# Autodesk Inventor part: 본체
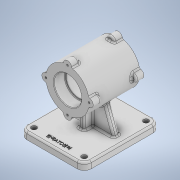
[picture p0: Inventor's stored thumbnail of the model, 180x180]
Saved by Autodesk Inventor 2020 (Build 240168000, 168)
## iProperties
Created: 2022-11
Part Number: 본체
Material: 일반
Document SubType Name: Modeling
Designer: owner
Density: 1 g/cm^3
Appearance: 기본값
Mass: 450.145 g
Surface Area: 796.917 cm^2
Volume: 450.145 cm^3
Author: owner
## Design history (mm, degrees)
sketch "스케치1"
  geometry: C1 r 37 at (0, 0); 1 further point
  constraints: 1 centre point, 1 coincident
  dimensions: "d0" = 74 diameter of C1
extrude "돌출1" new body sketch "스케치1" stored distance "d6" = 87; taper "d7" = 0 deg
sketch "스케치2"
  geometry: A1 r 37 centre (0, 0) between (36.338, 6.969) and (6.969, 36.338) reference; 2 further points
  constraints: 1 coincident
hole "구멍1" sketch "스케치2" at (0, 0) diameter "d8" = 42; stored, may be unused: countersink angle "d12" = 90 deg, drill point angle "d14" = 0 deg; dims "d9" = 8, "d10" = 47, "d11" = 19, "d13" = 10
sketch "스케치3"
  geometry: A1 r 37 centre (0, 0) between (36.338, 6.969) and (6.969, 36.338) reference; 2 further points
  constraints: 1 coincident
hole "구멍2" sketch "스케치3" at (0, 0) diameter "d15" = 42; stored, may be unused: countersink angle "d19" = 90 deg, drill point angle "d21" = 0 deg; dims "d16" = 8, "d17" = 47, "d18" = 19, "d20" = 10
node "작업 평면1"
sketch "스케치4"
  geometry: L1 (-55, 70)-(55, 70); L2 (55, 70)-(55, -60); L3 (55, -60)-(-55, -60); L4 (-55, -60)-(-55, 70); 2 further points
  constraints: 8 end point, 2 parallel, 1 horizontal, 1 midpoint, 1 perpendicular, 1 vertical alignment
  dimensions: "d23" = 110 distance of L2.end L3.end; "d24" = 130 distance of L1.end L2.end; "d25" = 70 distance from line of point (0, 0) L1
extrude "돌출2" join sketch "스케치4" distance "d26" = 12; taper "d27" = 0 deg
node "작업 평면2"
sketch "스케치5"
  geometry: L1 (14, 12)-(29.664, 55.036); L2 (110, 12)-(0, 12) reference; L3 (96, 12)-(80.336, 55.036); A1 r 37 centre (55, 82) between (29.664, 55.036) and (18.662, 75.031) reference; A2 r 37 centre (55, 82) between (80.336, 55.036) and (61.969, 45.662) reference; 4 further points
  constraints: 4 end point, 2 point on circle, 2 point on line, 1 equal length
  dimensions: "d29" = 14 distance of L1.start L2.end; "d30" = 14 distance of L3.start L2.start; "d31" = 110 deg angle of L2 L3
extrude "돌출3" join sketch "스케치5" stored distance "d32" = 10; taper "d33" = 0 deg
sketch "스케치6"
  geometry: C1 r 7 at (0, 37); C2 r 7 at (-37, 0); C3 r 7 at (0, -37); C4 r 7 at (37, 0); 10 further points
  constraints: 4 centre point, 1 vertical alignment, 11 other
  dimensions: "d34" = 14 diameter of C1; "d37" = 360 deg dimension on point (0, 0) C1.centre (derived)
extrude "돌출4" join sketch "스케치6" distance "d39" = 14; taper "d40" = 0 deg
sketch "스케치7"
  geometry: L1 (-70, -60)-(-70, 70) reference; L2 (-70, 20)-(-37, 20); L3 (-70, -20)-(-37, -20); L4 (-37, -43.5)-(-37, 29.5) reference; 1 further point
  constraints: 4 end point, 4 point on line, 2 horizontal
  dimensions: "d41" = 20 distance from line of L3 point (0, 0); "d42" = 40 distance between parallel lines of L2 L3
feature "리브1" sketch "스케치7" dims "d43" = 1, "d44" = 10, "d45" = 0, "d46" = 0, "d47" = 1, "d48" = 1
fillet "모깎기1" dims "d49" = 12
fillet "모깎기2" dims "d50" = 3
fillet "모깎기3" dims "d51" = 3
sketch "스케치8"
  geometry: A1 r 12 centre (-43, 48) between (-43, 60) and (-55, 48) reference; 2 further points
  constraints: 1 coincident
hole "구멍3" sketch "스케치8" at (-43, 48) diameter "d52" = 9; stored, may be unused: countersink angle "d56" = 90 deg, drill point angle "d58" = 0 deg; dims "d53" = 8, "d54" = 47, "d55" = 19, "d57" = 10
sketch "스케치9"
  geometry: A1 r 12 centre (-43, -58) between (-55, -58) and (-43, -70) reference; 2 further points
  constraints: 1 coincident
hole "구멍4" sketch "스케치9" at (-43, -58) diameter "d59" = 9; stored, may be unused: countersink angle "d63" = 90 deg, drill point angle "d65" = 0 deg; dims "d60" = 8, "d61" = 47, "d62" = 19, "d64" = 10
sketch "스케치10"
  geometry: A1 r 12 centre (43, -58) between (43, -70) and (55, -58) reference; 2 further points
  constraints: 1 coincident
hole "구멍5" sketch "스케치10" at (43, -58) diameter "d66" = 9; stored, may be unused: countersink angle "d70" = 90 deg, drill point angle "d72" = 0 deg; dims "d67" = 8, "d68" = 47, "d69" = 19, "d71" = 10
sketch "스케치11"
  geometry: A1 r 12 centre (43, 48) between (55, 48) and (43, 60) reference; 2 further points
  constraints: 1 coincident
hole "구멍6" sketch "스케치11" at (43, 48) diameter "d73" = 9; stored, may be unused: countersink angle "d77" = 90 deg, drill point angle "d79" = 0 deg; dims "d74" = 8, "d75" = 47, "d76" = 19, "d78" = 10
node "스케치12"
sketch "스케치13"
  geometry: A1 r 7 centre (0, 37) between (6.889, 38.239) and (-6.889, 38.239) reference; 2 further points
  constraints: 1 coincident
hole "구멍7" sketch "스케치13" at (0, 37) diameter "d80" = 3.242; stored, may be unused: countersink angle "d84" = 90 deg, drill point angle "d86" = 118 deg; dims "d81" = 8, "d82" = 47, "d83" = 19, "d85" = 10
fillet "모깎기4" dims "d90" = 3
fillet "모깎기5" dims "d91" = 3
fillet "모깎기6" dims "d92" = 3
chamfer "모따기1" distance "d93" = 1; stored, may be unused: second distance "d94" = 2, angle "d95" = 45 deg
fillet "모깎기7" dims "d96" = 1
sketch "스케치14"
  geometry: L1 (-43, -70)-(43, -70) reference; 2 further points
  constraints: 1 vertical alignment, 1 other
  dimensions: "d97" = 12 distance from line of L1 point (0, -58)
feature "엠보싱1" sketch "스케치14" dims "d23" = 110, "d24" = 130, "d25" = 70, "d98" = 0.5, "d99" = 0
node "솔리드1"
mirror "미러2"
pattern_circular "원형 패턴1" dims angle "d88" = 360 deg
mirror "미러4"
mirror "미러5"
feature "A9D066F2-1C7D-4E18-AEED-F7BC21143FA4" dims "d8" = 42, "d9" = 8, "d10" = 47, "d11" = 19, "d12" = 90 deg, "d13" = 10, "d14" = 0
other parameters: "d22" = -82
